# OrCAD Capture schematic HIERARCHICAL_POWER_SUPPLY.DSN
size A
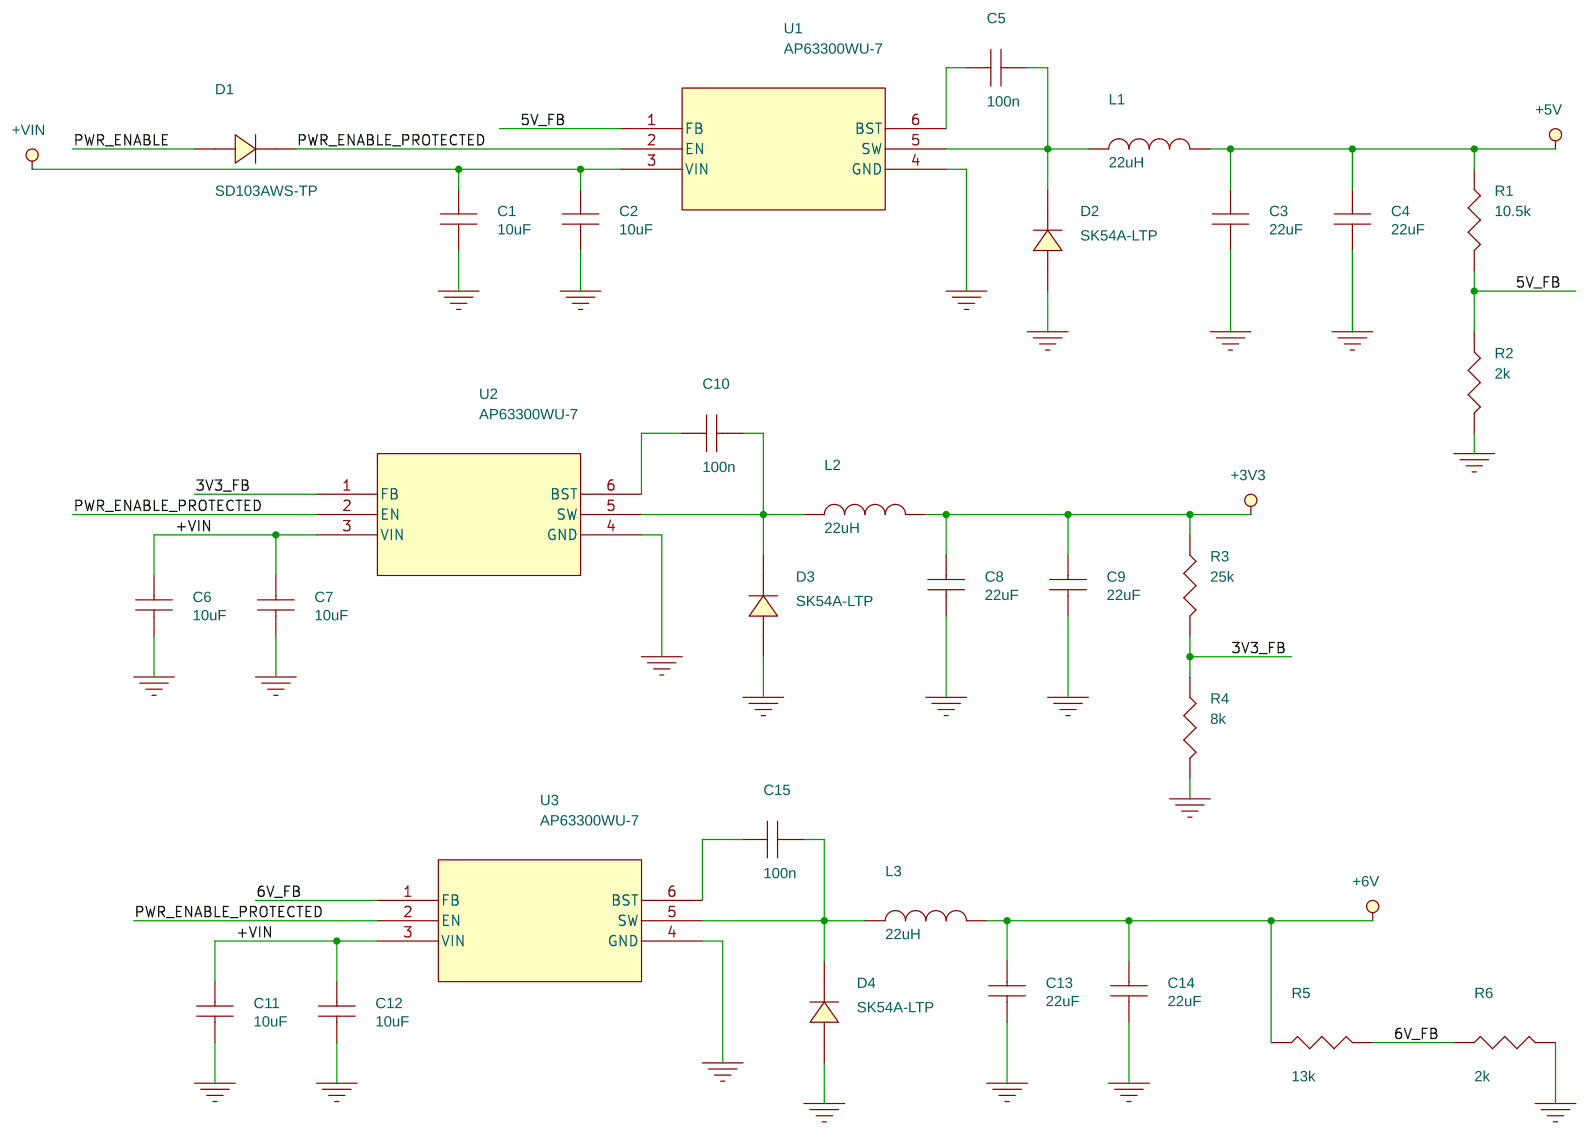
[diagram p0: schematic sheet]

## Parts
C1  10uF
C2  10uF
C3  22uF
C4  22uF
C5  100n
C6  10uF
C7  10uF
C8  22uF
C9  22uF
C10  100n
C11  10uF
C12  10uF
C13  22uF
C14  22uF
C15  100n
D1  SD103AWS-TP
D2  SK54A-LTP
D3  SK54A-LTP
D4  SK54A-LTP
L1  22uH
L2  22uH
L3  22uH
R1  10.5k
R2  2k
R3  25k
R4  8k
R5  13k
R6  2k
U1  AP63300WU-7  [TSOT6_AP63300WU-7_DIO]
U2  AP63300WU-7  [TSOT6_AP63300WU-7_DIO]
U3  AP63300WU-7  [TSOT6_AP63300WU-7_DIO]

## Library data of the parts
C1-C15 = CAP_NP
D1-D4 = DIODE
L1-L3 = INDUCTOR
R1-R6 = RESISTOR
U1-U3 = AP63300WU-7

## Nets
3V3_FB: R3.2 R4.1 U2.1(FB)
5V_FB: R1.2 R2.1 U1.1(FB)
6V_FB: R5.2 R6.1 U3.1(FB)
+3V3: C8.1 C9.1 L2.2 R3.1
+5V: C3.1 C4.1 L1.2 R1.1
+6V: C13.1 C14.1 L3.2 R5.1
+VIN: C1.1 C2.1 C6.1 C7.1 C11.1 C12.1 U1.3(VIN) U2.3(VIN) U3.3(VIN)
GND: C1.2 C2.2 C3.2 C4.2 C6.2 C7.2 C8.2 C9.2 C11.2 C12.2 C13.2 C14.2 D2.2(A) D3.2(A) D4.2(A) R2.2 R4.2 R6.2 U1.4(GND) U2.4(GND) U3.4(GND)
PWR_ENABLE: D1.2(A)
PWR_ENABLE_PROTECTED: D1.1(K) U1.2(EN) U2.2(EN) U3.2(EN)
N00568: C5.1 U1.6(BST)
N00575: C5.2 D2.1(K) L1.1 U1.5(SW)
N01451: C10.2 D3.1(K) L2.1 U2.5(SW)
N01604: C10.1 U2.6(BST)
N02471: C15.2 D4.1(K) L3.1 U3.5(SW)
N02754: C15.1 U3.6(BST)
